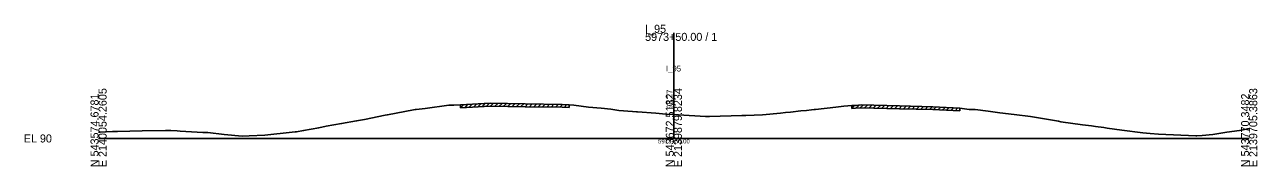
# Model space of a CAD drawing. Extents: x -12534 to 3403, y -1332 to 21983.
# Drawn here: x -25.7 to 402.8, y 8490.3 to 8539.5 of the extents above; entities that cross this region are included whole.
import ezdxf

# ---------------------------------------------------------------- set-up
doc = ezdxf.new("R2010")
doc.units = 0
for name, color, linetype in [('RD_GPK_XS_Cell', 7, 'Continuous'), ('RD_XS_ExGround', 7, 'Continuous'), ('RD_XS_ExPaveRet', 7, 'Continuous'), ('RD_XS_TX_Baseline', 7, 'Continuous'), ('RD_XS_TX_Elev_EX', 7, 'Continuous'), ('RD_XS_TX_Station', 7, 'Continuous')]:
    doc.layers.add(name, color=color, linetype=linetype)

msp = doc.modelspace()

# ---------------------------------------------------------------- linework, layer by layer
at = {"layer": 'RD_GPK_XS_Cell'}
for p, q in [((200, 8500), (200, 8536.7)), ((0, 8500), (200, 8500)), ((200, 8500), (400, 8500))]:
    msp.add_line(p, q, dxfattribs=at)
at = {"layer": 'RD_XS_ExGround'}
msp.add_lwpolyline([(0, 8502.21), (0.58, 8502.22), (4.79, 8502.38), (6.6, 8502.37), (15.14, 8502.6), (23.3, 8502.78), (25.13, 8502.78), (27.35, 8502.66), (28.4, 8502.51), (36.25, 8502.11), (37.93, 8502.01), (43.72, 8501.41), (49.94, 8500.76), (52.35, 8500.89), (57.82, 8501.14), (67.25, 8502.18), (68.38, 8502.29), (68.8, 8502.35), (71.29, 8502.75), (76.57, 8503.74), (79.14, 8504.21), (84.46, 8505.14), (89.67, 8506.12), (92.41, 8506.64), (99.6, 8508.05), (100.43, 8508.21), (109.43, 8509.9), (110.02, 8510.01), (110.45, 8510.1), (113.56, 8510.46), (121.72, 8511.54), (123.49, 8511.62), (125.81, 8511.65), (136.08, 8512.23), (148.33, 8512.04), (161.19, 8511.82), (163.63, 8511.72), (165.2, 8511.51), (170.29, 8510.91), (174.74, 8510.49), (178.06, 8510.12), (180.87, 8509.75), (185.63, 8509.34), (186.96, 8509.24), (187.4, 8509.22), (193.73, 8508.78), (197.23, 8508.44), (200, 8508.27), (201.65, 8508.17), (211.01, 8507.65), (212.4, 8507.61), (223.63, 8507.94), (224.98, 8508.02), (230.82, 8508.16), (237.09, 8508.8), (238.85, 8508.99), (240.59, 8509.17), (244.12, 8509.57), (246.11, 8509.76), (247.9, 8509.92), (248.78, 8510.03), (249.29, 8510.09), (256.31, 8510.91), (259.11, 8511.22), (261.81, 8511.43), (263.12, 8511.48), (265.16, 8511.64), (278.4, 8511.33), (289.99, 8511.03), (299.42, 8510.56), (302.6, 8510.1), (303.55, 8510.05), (304.76, 8510.01), (309.21, 8509.45), (313.29, 8508.94), (318.31, 8508.34), (323.95, 8507.68), (333.74, 8505.97), (334.5, 8505.83), (342.06, 8504.78), (345.22, 8504.38), (346.54, 8504.19), (349.49, 8503.78), (350.59, 8503.6), (355.76, 8502.84), (363.01, 8501.98), (365.6, 8501.67), (368.47, 8501.52), (381.5, 8500.94), (381.84, 8500.91), (383.61, 8501.07), (387.32, 8501.36), (392.27, 8502.13), (396.62, 8502.8), (397.81, 8502.98), (400, 8503.4)], dxfattribs=at)
at = {"layer": 'RD_XS_ExPaveRet'}
for p, q in [((125.81, 8510.65), (126.87, 8511.71)), ((125.81, 8510.65), (125.81, 8511.65)), ((125.81, 8510.65), (136.08, 8511.23)), ((127.31, 8510.74), (128.37, 8511.8)), ((128.81, 8510.82), (129.87, 8511.88)), ((130.31, 8510.91), (131.37, 8511.97)), ((131.81, 8510.99), (132.87, 8512.05)), ((133.31, 8511.08), (134.37, 8512.14)), ((134.81, 8511.16), (135.87, 8512.22)), ((136.08, 8511.23), (148.33, 8511.04)), ((136.31, 8511.23), (137.29, 8512.21)), ((137.81, 8511.21), (138.79, 8512.19)), ((139.31, 8511.18), (140.29, 8512.17)), ((140.81, 8511.16), (141.79, 8512.14)), ((142.31, 8511.13), (143.29, 8512.12)), ((143.81, 8511.11), (144.79, 8512.09)), ((145.31, 8511.08), (146.29, 8512.07)), ((146.81, 8511.06), (147.79, 8512.04)), ((148.31, 8511.04), (149.29, 8512.02)), ((148.33, 8511.04), (161.19, 8510.82)), ((149.81, 8511.01), (150.79, 8511.99)), ((151.31, 8510.98), (152.29, 8511.97)), ((152.81, 8510.96), (153.79, 8511.94)), ((154.31, 8510.93), (155.29, 8511.92)), ((155.81, 8510.91), (156.79, 8511.89)), ((157.31, 8510.88), (158.29, 8511.87)), ((158.81, 8510.86), (159.79, 8511.84)), ((160.31, 8510.83), (161.29, 8511.81)), ((161.19, 8510.82), (163.63, 8510.72)), ((161.81, 8510.79), (162.77, 8511.75)), ((163.63, 8511.72), (163.63, 8510.72)), ((261.81, 8510.43), (262.84, 8511.47)), ((261.81, 8510.43), (261.81, 8511.43)), ((263.31, 8510.49), (264.39, 8511.58)), ((264.81, 8510.61), (265.82, 8511.62)), ((266.31, 8510.61), (267.28, 8511.59)), ((267.81, 8510.57), (268.78, 8511.55)), ((269.31, 8510.54), (270.28, 8511.52)), ((270.81, 8510.51), (271.78, 8511.48)), ((272.31, 8510.47), (273.28, 8511.45)), ((273.81, 8510.44), (274.78, 8511.41)), ((275.31, 8510.4), (276.28, 8511.38)), ((276.81, 8510.37), (277.78, 8511.34)), ((278.31, 8510.33), (279.28, 8511.31)), ((279.81, 8510.29), (280.78, 8511.27)), ((281.31, 8510.25), (282.28, 8511.23)), ((282.81, 8510.22), (283.78, 8511.19)), ((284.31, 8510.18), (285.28, 8511.15)), ((285.81, 8510.14), (286.78, 8511.11)), ((287.31, 8510.1), (288.28, 8511.07)), ((288.81, 8510.06), (289.78, 8511.03)), ((290.31, 8510.01), (291.26, 8510.96)), ((291.81, 8509.94), (292.76, 8510.89)), ((293.31, 8509.86), (294.26, 8510.81)), ((294.81, 8509.79), (295.76, 8510.74)), ((296.31, 8509.71), (297.26, 8510.66)), ((261.81, 8510.43), (263.12, 8510.48)), ((263.12, 8510.48), (265.16, 8510.64)), ((265.16, 8510.64), (278.4, 8510.33)), ((278.4, 8510.33), (289.99, 8510.03)), ((289.99, 8510.03), (299.42, 8509.56)), ((297.81, 8509.64), (298.76, 8510.59)), ((299.42, 8510.56), (299.42, 8509.56))]:
    msp.add_line(p, q, dxfattribs=at)

# ---------------------------------------------------------------- texts
at = {"layer": 'RD_GPK_XS_Cell'}
for s, p in [('5973+50.00 / 1', (190, 8533.9)), ('I_95', (190, 8536.7)), ('EL 90', (-26, 8498.6))]:
    msp.add_text(s, height=2.8, dxfattribs=at).set_placement(p)
for s, p in [('N 543574.6781', (0, 8490)), ('E 2140054.2605', (2.8, 8490)), ('N 543672.5132', (200, 8490)), ('E 2139879.8234', (202.8, 8490)), ('N 543770.3482', (400, 8490)), ('E 2139705.3863', (402.8, 8490))]:
    msp.add_text(s, height=2.8, rotation=90, dxfattribs=at).set_placement(p)
at = {"layer": 'RD_XS_TX_Baseline'}
msp.add_text('I_95', height=2, dxfattribs=at).set_placement((197.28, 8523.27))
at = {"layer": 'RD_XS_TX_Elev_EX'}
msp.add_text('98.27', height=2, rotation=90, dxfattribs=at).set_placement((199.5, 8510.27))
at = {"layer": 'RD_XS_TX_Station'}
msp.add_text('5973+50.00', height=1.5, dxfattribs=at).set_placement((194.51, 8498.27))

doc.saveas('drawing.dxf')
